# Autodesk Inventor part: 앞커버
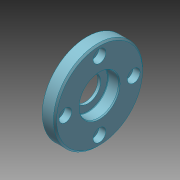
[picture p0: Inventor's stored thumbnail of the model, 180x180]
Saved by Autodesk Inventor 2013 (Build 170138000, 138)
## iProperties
Created: 2024-01
Part Number: 앞커버
Material: 알루미늄 6061
Document SubType Name: Modeling
Designer: mdu-01
Density: 1 g/cm^3
Author: mdu-01
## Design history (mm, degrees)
sketch "스케치1"
  geometry: L1 (0, 0)-(-9, 0); L2 (-9, 0)-(-9, 14.5); L3 (-9, 14.5)-(-12, 14.5); L4 (-12, 14.5)-(-12, 16.5); L5 (-11, 17.5)-(-8, 17.5); L6 (-8, 17.5)-(-8, 28); L7 (-8, 28)-(-1, 28); L8 (0, 27)-(0, 0); L9 (-12, 16.5)-(-11, 17.5); L10 (-1, 28)-(0, 27); 2 further points
  constraints: 20 end point, 6 parallel, 4 point on line, 1 horizontal, 1 perpendicular
  dimensions: "d0" = 56 diameter of L7 L1; "d2" = 8 distance between parallel lines of L8 L6; "d3" = 3 distance between parallel lines of L2 L4; "d4" = 4 distance between parallel lines of L6 L4; "d5" = 29 diameter of L3 L1; "d6" = 35 diameter of L5 L1; "d7" = 1 distance of L4.end point (-12, 17.5); "d8" = 1 distance of L5.start point (-12, 17.5) (= d7); "d9" = 1 distance of L7.end point (0, 28) (= d7); "d10" = 1 distance of L8.start point (0, 28) (= d9)
revolve "회전1" sketch "스케치1" stored, may be unused: angle "d11" = 90 deg
sketch "스케치2" dims "d12" = 43
  geometry: 3 further points
  constraints: 2 vertical alignment, 1 coincident, 2 other
hole "구멍1" sketch "스케치2" at (0, 21.5) diameter "d13" = 4.5; stored, may be unused: countersink angle "d17" = 90 deg, drill point angle "d19" = 118 deg; dims "d14" = 6, "d15" = 8, "d16" = 4.4, "d18" = 8
sketch "스케치3"
  geometry: L1 (-9, -14.5)-(-9, 14.5) reference; L2 (0, -27)-(0, 27) reference; L3 (-9, 0)-(0, 0); L4 (0, 12.904)-(-0.7, 12.5); L5 (-0.7, 12.5)-(-7, 12.5); L6 (-7.3, 12.2)-(-7.3, 8); L7 (-7.3, 8)-(-9, 8); A1 r 0.3 centre (-7, 12.2) between (-7, 12.5) and (-7.3, 12.2)
  constraints: 10 end point, 3 perpendicular, 2 point on circle, 2 point on line, 2 tangent, 1 centre point, 1 midpoint, 1 parallel
  dimensions: "d23" = 30 deg angle of L5 L4; "d24" = 0.7 distance from line of L4.end L2; "d25" = 7.3 distance between parallel lines of L6 L2; "d26" = 25 diameter of L5 L3; "d27" = 0.3 radius of A1; "d28" = 16 diameter of L7 L3
revolve "회전2" sketch "스케치3" stored, may be unused: angle "d29" = 90 deg
node "솔리드1"
pattern_circular "원형 패턴1" dims angle "d21" = 360 deg
